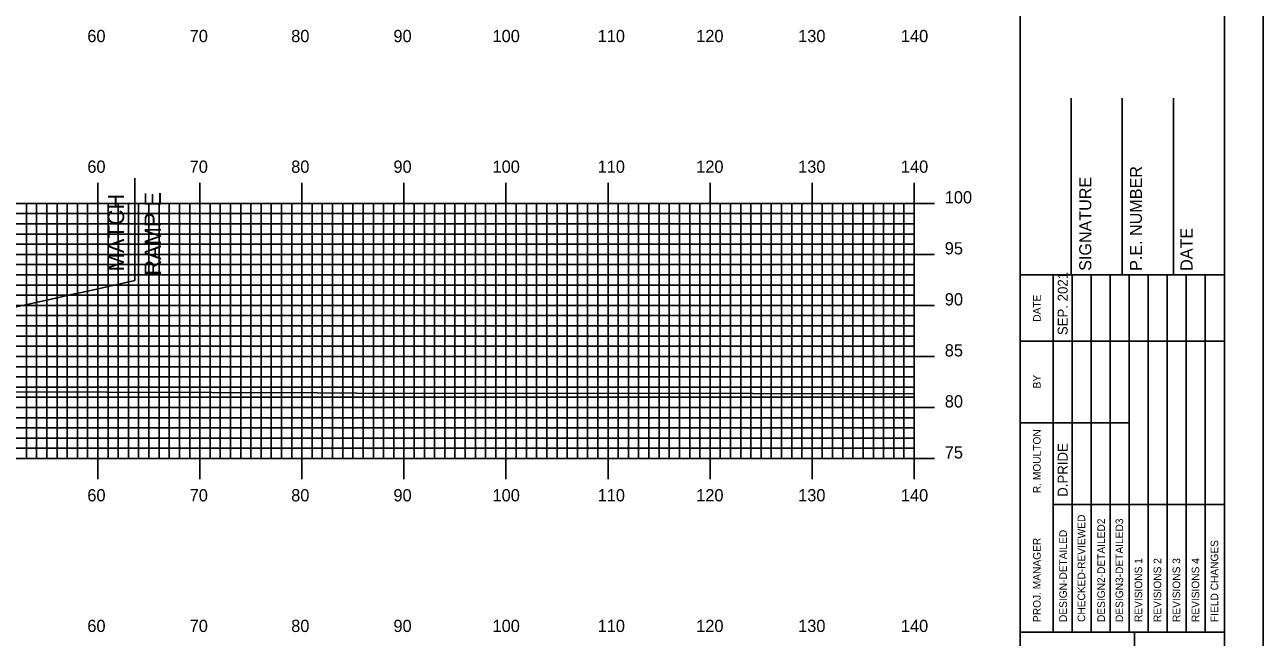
# Model space of a CAD drawing. Extents: x 1757069 to 1757412, y 442591 to 442811.
# Drawn here: x 1757287.4 to 1757408.8, y 442686.2 to 442746.2 of the extents above; entities that cross this region are included whole.
import ezdxf

# ---------------------------------------------------------------- set-up
doc = ezdxf.new("R2010")
doc.units = 0
for name, color, linetype in [('ANNOTATION', 7, 'Continuous'), ('BORDER', 7, 'Continuous'), ('D_Roadway_Centerline', 7, 'Continuous'), ('D_Roadway_SubGrade', 7, 'Continuous'), ('H_V ANNOTATION', 7, 'Continuous'), ('MAJOR', 7, 'Continuous'), ('MINOR', 7, 'Continuous'), ('PLOT BOUNDARY', 7, 'Continuous'), ('S_Roadway_Centerline', 7, 'Continuous')]:
    doc.layers.add(name, color=color, linetype=linetype)

msp = doc.modelspace()

# ---------------------------------------------------------------- linework, layer by layer
at = {"layer": 'BORDER'}
for p, q in [((1757385, 442596.67), (1757385, 442806.67)), ((1757390, 442721.67), (1757390, 442738.97)), ((1757395, 442721.67), (1757395, 442738.97)), ((1757400, 442721.67), (1757400, 442738.97)), ((1757385, 442721.67), (1757405, 442721.67)), ((1757385, 442686.67), (1757405, 442686.67)), ((1757396.18, 442616.67), (1757396.18, 442686.67))]:
    msp.add_line(p, q, dxfattribs=at)
msp.add_lwpolyline([(1757085, 442596.67), (1757405, 442596.67), (1757405, 442806.67), (1757085, 442806.67)], close=True, dxfattribs=at)
for points in [[(1757388.23, 442715.17), (1757388.23, 442721.67)], [(1757390.09, 442686.68), (1757390.09, 442721.67)], [(1757391.95, 442721.67), (1757391.95, 442686.68)], [(1757393.82, 442686.68), (1757393.82, 442721.67)], [(1757395.68, 442686.68), (1757395.68, 442721.67)], [(1757397.54, 442686.68), (1757397.54, 442721.67)], [(1757399.41, 442686.68), (1757399.41, 442721.67)], [(1757401.27, 442686.68), (1757401.27, 442721.67)], [(1757403.13, 442686.68), (1757403.13, 442721.67)], [(1757388.23, 442686.68), (1757388.23, 442720.26)], [(1757385, 442715.17), (1757405, 442715.17)], [(1757385, 442707.17), (1757388.23, 442707.17)], [(1757388.23, 442707.17), (1757395.68, 442707.17)], [(1757388.23, 442699.17), (1757405, 442699.17)]]:
    msp.add_lwpolyline(points, dxfattribs=at)
at = {"layer": 'D_Roadway_Centerline'}
msp.add_lwpolyline([(1757276.03, 442716.15), (1757277.4, 442716.46), (1757279.51, 442716.93), (1757279.72, 442716.98), (1757280.6, 442717.17), (1757280.87, 442717.24), (1757282.31, 442717.56), (1757282.61, 442717.63), (1757285.08, 442718.18), (1757285.17, 442718.2), (1757286.34, 442718.46), (1757287.81, 442718.79), (1757289.74, 442719.22), (1757290.5, 442719.39), (1757290.58, 442719.41), (1757290.73, 442719.44), (1757292.02, 442719.73), (1757293.15, 442719.98), (1757295.07, 442720.4), (1757295.77, 442720.56), (1757298.22, 442721.11)], dxfattribs=at)
at = {"layer": 'D_Roadway_SubGrade'}
msp.add_line((1757298.22, 442731.15), (1757298.22, 442721.11), dxfattribs=at)
at = {"layer": 'MAJOR'}
for p, q in [((1757294.6, 442730.67), (1757294.6, 442728.67)), ((1757304.6, 442730.67), (1757304.6, 442728.67)), ((1757314.6, 442730.67), (1757314.6, 442728.67)), ((1757324.6, 442730.67), (1757324.6, 442728.67)), ((1757334.6, 442730.67), (1757334.6, 442728.67)), ((1757344.6, 442730.67), (1757344.6, 442728.67)), ((1757354.6, 442730.67), (1757354.6, 442728.67)), ((1757364.6, 442730.67), (1757364.6, 442728.67)), ((1757374.6, 442730.67), (1757374.6, 442728.67)), ((1757094.6, 442728.67), (1757374.6, 442728.67)), ((1757094.6, 442728.67), (1757374.6, 442728.67)), ((1757294.6, 442703.67), (1757294.6, 442728.67)), ((1757304.6, 442703.67), (1757304.6, 442728.67)), ((1757314.6, 442703.67), (1757314.6, 442728.67)), ((1757324.6, 442703.67), (1757324.6, 442728.67)), ((1757334.6, 442703.67), (1757334.6, 442728.67)), ((1757344.6, 442703.67), (1757344.6, 442728.67)), ((1757354.6, 442703.67), (1757354.6, 442728.67)), ((1757364.6, 442703.67), (1757364.6, 442728.67)), ((1757376.6, 442728.67), (1757372.59, 442728.67)), ((1757374.6, 442703.67), (1757374.6, 442728.67)), ((1757374.6, 442703.67), (1757374.6, 442728.67)), ((1757094.6, 442723.67), (1757374.6, 442723.67)), ((1757376.6, 442723.67), (1757372.59, 442723.67)), ((1757094.6, 442718.67), (1757374.6, 442718.67)), ((1757376.6, 442718.67), (1757372.59, 442718.67)), ((1757094.6, 442713.67), (1757374.6, 442713.67)), ((1757376.6, 442713.67), (1757372.59, 442713.67)), ((1757094.6, 442708.67), (1757374.6, 442708.67)), ((1757376.6, 442708.67), (1757372.59, 442708.67)), ((1757094.6, 442703.67), (1757374.6, 442703.67)), ((1757094.6, 442703.67), (1757374.6, 442703.67)), ((1757294.6, 442701.66), (1757294.6, 442703.67)), ((1757304.6, 442701.66), (1757304.6, 442703.67)), ((1757314.6, 442701.66), (1757314.6, 442703.67)), ((1757324.6, 442701.66), (1757324.6, 442703.67)), ((1757334.6, 442701.66), (1757334.6, 442703.67)), ((1757344.6, 442701.66), (1757344.6, 442703.67)), ((1757354.6, 442701.66), (1757354.6, 442703.67)), ((1757364.6, 442701.66), (1757364.6, 442703.67)), ((1757376.6, 442703.67), (1757372.59, 442703.67)), ((1757374.6, 442701.66), (1757374.6, 442703.67))]:
    msp.add_line(p, q, dxfattribs=at)
at = {"layer": 'MINOR'}
for p, q in [((1757287.6, 442703.67), (1757287.6, 442728.67)), ((1757288.6, 442703.67), (1757288.6, 442728.67)), ((1757289.6, 442703.67), (1757289.6, 442728.67)), ((1757290.6, 442703.67), (1757290.6, 442728.67)), ((1757291.6, 442703.67), (1757291.6, 442728.67)), ((1757292.6, 442703.67), (1757292.6, 442728.67)), ((1757293.6, 442703.67), (1757293.6, 442728.67)), ((1757295.6, 442703.67), (1757295.6, 442728.67)), ((1757296.6, 442703.67), (1757296.6, 442728.67)), ((1757297.6, 442703.67), (1757297.6, 442728.67)), ((1757298.6, 442703.67), (1757298.6, 442728.67)), ((1757299.6, 442703.67), (1757299.6, 442728.67)), ((1757300.6, 442703.67), (1757300.6, 442728.67)), ((1757301.6, 442703.67), (1757301.6, 442728.67)), ((1757302.6, 442703.67), (1757302.6, 442728.67)), ((1757303.6, 442703.67), (1757303.6, 442728.67)), ((1757305.6, 442703.67), (1757305.6, 442728.67)), ((1757306.6, 442703.67), (1757306.6, 442728.67)), ((1757307.6, 442703.67), (1757307.6, 442728.67)), ((1757308.6, 442703.67), (1757308.6, 442728.67)), ((1757309.6, 442703.67), (1757309.6, 442728.67)), ((1757310.6, 442703.67), (1757310.6, 442728.67)), ((1757311.6, 442703.67), (1757311.6, 442728.67)), ((1757312.6, 442703.67), (1757312.6, 442728.67)), ((1757313.6, 442703.67), (1757313.6, 442728.67)), ((1757315.6, 442703.67), (1757315.6, 442728.67)), ((1757316.6, 442703.67), (1757316.6, 442728.67)), ((1757317.6, 442703.67), (1757317.6, 442728.67)), ((1757318.6, 442703.67), (1757318.6, 442728.67)), ((1757319.6, 442703.67), (1757319.6, 442728.67)), ((1757320.6, 442703.67), (1757320.6, 442728.67)), ((1757321.6, 442703.67), (1757321.6, 442728.67)), ((1757322.6, 442703.67), (1757322.6, 442728.67)), ((1757323.6, 442703.67), (1757323.6, 442728.67)), ((1757325.6, 442703.67), (1757325.6, 442728.67)), ((1757326.6, 442703.67), (1757326.6, 442728.67)), ((1757327.6, 442703.67), (1757327.6, 442728.67)), ((1757328.6, 442703.67), (1757328.6, 442728.67)), ((1757329.6, 442703.67), (1757329.6, 442728.67)), ((1757330.6, 442703.67), (1757330.6, 442728.67)), ((1757331.6, 442703.67), (1757331.6, 442728.67)), ((1757332.6, 442703.67), (1757332.6, 442728.67)), ((1757333.6, 442703.67), (1757333.6, 442728.67)), ((1757335.6, 442703.67), (1757335.6, 442728.67)), ((1757336.6, 442703.67), (1757336.6, 442728.67)), ((1757337.6, 442703.67), (1757337.6, 442728.67)), ((1757338.6, 442703.67), (1757338.6, 442728.67)), ((1757339.6, 442703.67), (1757339.6, 442728.67)), ((1757340.6, 442703.67), (1757340.6, 442728.67)), ((1757341.6, 442703.67), (1757341.6, 442728.67)), ((1757342.6, 442703.67), (1757342.6, 442728.67)), ((1757343.6, 442703.67), (1757343.6, 442728.67)), ((1757345.6, 442703.67), (1757345.6, 442728.67)), ((1757346.6, 442703.67), (1757346.6, 442728.67)), ((1757347.6, 442703.67), (1757347.6, 442728.67)), ((1757348.6, 442703.67), (1757348.6, 442728.67)), ((1757349.6, 442703.67), (1757349.6, 442728.67)), ((1757350.6, 442703.67), (1757350.6, 442728.67)), ((1757351.6, 442703.67), (1757351.6, 442728.67)), ((1757352.6, 442703.67), (1757352.6, 442728.67)), ((1757353.6, 442703.67), (1757353.6, 442728.67)), ((1757355.6, 442703.67), (1757355.6, 442728.67)), ((1757356.6, 442703.67), (1757356.6, 442728.67)), ((1757357.6, 442703.67), (1757357.6, 442728.67)), ((1757358.6, 442703.67), (1757358.6, 442728.67)), ((1757359.6, 442703.67), (1757359.6, 442728.67)), ((1757360.6, 442703.67), (1757360.6, 442728.67)), ((1757361.6, 442703.67), (1757361.6, 442728.67)), ((1757362.6, 442703.67), (1757362.6, 442728.67)), ((1757363.6, 442703.67), (1757363.6, 442728.67)), ((1757365.6, 442703.67), (1757365.6, 442728.67)), ((1757366.6, 442703.67), (1757366.6, 442728.67)), ((1757367.6, 442703.67), (1757367.6, 442728.67)), ((1757368.6, 442703.67), (1757368.6, 442728.67)), ((1757369.6, 442703.67), (1757369.6, 442728.67)), ((1757370.6, 442703.67), (1757370.6, 442728.67)), ((1757371.6, 442703.67), (1757371.6, 442728.67)), ((1757372.6, 442703.67), (1757372.6, 442728.67)), ((1757373.6, 442703.67), (1757373.6, 442728.67)), ((1757094.6, 442727.67), (1757374.6, 442727.67)), ((1757094.6, 442726.67), (1757374.6, 442726.67)), ((1757374.6, 442727.67), (1757372.59, 442727.67)), ((1757374.6, 442726.67), (1757372.59, 442726.67)), ((1757094.6, 442725.67), (1757374.6, 442725.67)), ((1757374.6, 442725.67), (1757372.59, 442725.67)), ((1757094.6, 442724.67), (1757374.6, 442724.67)), ((1757374.6, 442724.67), (1757372.59, 442724.67)), ((1757094.6, 442722.67), (1757374.6, 442722.67)), ((1757374.6, 442722.67), (1757372.59, 442722.67)), ((1757094.6, 442721.67), (1757374.6, 442721.67)), ((1757094.6, 442720.67), (1757374.6, 442720.67)), ((1757374.6, 442721.67), (1757372.59, 442721.67)), ((1757374.6, 442720.67), (1757372.59, 442720.67)), ((1757094.6, 442719.67), (1757374.6, 442719.67)), ((1757374.6, 442719.67), (1757372.59, 442719.67)), ((1757094.6, 442717.67), (1757374.6, 442717.67)), ((1757374.6, 442717.67), (1757372.59, 442717.67)), ((1757094.6, 442716.67), (1757374.6, 442716.67)), ((1757094.6, 442715.67), (1757374.6, 442715.67)), ((1757374.6, 442716.67), (1757372.59, 442716.67)), ((1757374.6, 442715.67), (1757372.59, 442715.67)), ((1757094.6, 442714.67), (1757374.6, 442714.67)), ((1757374.6, 442714.67), (1757372.59, 442714.67)), ((1757094.6, 442712.67), (1757374.6, 442712.67)), ((1757374.6, 442712.67), (1757372.59, 442712.67)), ((1757094.6, 442711.67), (1757374.6, 442711.67)), ((1757374.6, 442711.67), (1757372.59, 442711.67)), ((1757094.6, 442710.67), (1757374.6, 442710.67)), ((1757094.6, 442709.67), (1757374.6, 442709.67)), ((1757374.6, 442710.67), (1757372.59, 442710.67)), ((1757374.6, 442709.67), (1757372.59, 442709.67)), ((1757094.6, 442707.67), (1757374.6, 442707.67)), ((1757374.6, 442707.67), (1757372.59, 442707.67)), ((1757094.6, 442706.67), (1757374.6, 442706.67)), ((1757374.6, 442706.67), (1757372.59, 442706.67)), ((1757094.6, 442705.67), (1757374.6, 442705.67)), ((1757374.6, 442705.67), (1757372.59, 442705.67)), ((1757094.6, 442704.67), (1757374.6, 442704.67)), ((1757374.6, 442704.67), (1757372.59, 442704.67))]:
    msp.add_line(p, q, dxfattribs=at)
at = {"layer": 'PLOT BOUNDARY'}
msp.add_lwpolyline([(1757068.81, 442590.55), (1757408.81, 442590.55), (1757408.81, 442810.55), (1757068.81, 442810.55)], close=True, dxfattribs=at)
at = {"layer": 'S_Roadway_Centerline'}
msp.add_lwpolyline([(1757094.6, 442709.18), (1757117.33, 442709.26), (1757140.81, 442709.08), (1757149.64, 442709.11), (1757165.92, 442709.27), (1757181.5, 442709.37), (1757191.75, 442709.55), (1757206.83, 442709.71), (1757242.69, 442709.94), (1757244.49, 442709.95), (1757245.67, 442709.95), (1757285.02, 442710.21), (1757285.15, 442710.21), (1757316.08, 442710.1), (1757319.99, 442710.08), (1757358.79, 442710.05), (1757374.6, 442710.01)], dxfattribs=at)

# ---------------------------------------------------------------- texts
at = {"layer": 'ANNOTATION'}
for s, p in [('MATCH', (1757297.18, 442722.01)), ('RAMP E', (1757300.78, 442721.59))]:
    msp.add_text(s, height=1.6, rotation=90, dxfattribs=at).set_placement(p)
at = {"layer": 'BORDER'}
for s, height, p in [('P.E. NUMBER', 1.1811, (1757396.92, 442722.06)), ('SIGNATURE', 1.181, (1757391.96, 442722.06)), ('DATE', 1.181, (1757401.88, 442722.06)), ('SEP. 2021', 0.969, (1757389.64, 442715.76)), ('DATE', 0.743, (1757387, 442717.08)), ('BY', 0.743, (1757387, 442710.54)), ('R. MOULTON', 0.745, (1757387, 442700.28)), ('D.PRIDE', 0.969, (1757389.64, 442699.92)), ('CHECKED-REVIEWED', 0.7455, (1757391.36, 442687.65)), ('DESIGN2-DETAILED2', 0.7455, (1757393.3, 442687.65)), ('DESIGN3-DETAILED3', 0.7455, (1757395.08, 442687.65)), ('DESIGN-DETAILED', 0.7455, (1757389.57, 442687.65)), ('PROJ. MANAGER', 0.7455, (1757387, 442687.65)), ('FIELD CHANGES', 0.7455, (1757404.4, 442687.65)), ('REVISIONS 1', 0.7455, (1757396.95, 442687.65)), ('REVISIONS 2', 0.7455, (1757398.81, 442687.65)), ('REVISIONS 3', 0.7455, (1757400.67, 442687.65)), ('REVISIONS 4', 0.7455, (1757402.54, 442687.65))]:
    msp.add_text(s, height=height, rotation=90, dxfattribs=at).set_placement(p)
at = {"layer": 'H_V ANNOTATION'}
for s, p in [('60', (1757293.57, 442744.47)), ('70', (1757303.6, 442744.47)), ('80', (1757313.55, 442744.47)), ('90', (1757323.57, 442744.47)), ('100', (1757333.28, 442744.47)), ('110', (1757343.58, 442744.47)), ('120', (1757353.24, 442744.47)), ('130', (1757363.23, 442744.47)), ('140', (1757373.3, 442744.47)), ('60', (1757293.57, 442731.67)), ('70', (1757303.6, 442731.67)), ('80', (1757313.55, 442731.67)), ('90', (1757323.57, 442731.67)), ('100', (1757333.28, 442731.67)), ('110', (1757343.58, 442731.67)), ('120', (1757353.24, 442731.67)), ('130', (1757363.23, 442731.67)), ('140', (1757373.3, 442731.67)), ('100', (1757377.6, 442728.67)), ('95', (1757377.6, 442723.67)), ('90', (1757377.6, 442718.67)), ('85', (1757377.6, 442713.67)), ('80', (1757377.6, 442708.67)), ('75', (1757377.6, 442703.67)), ('60', (1757293.57, 442699.47)), ('70', (1757303.6, 442699.47)), ('80', (1757313.55, 442699.47)), ('90', (1757323.57, 442699.47)), ('100', (1757333.28, 442699.47)), ('110', (1757343.58, 442699.47)), ('120', (1757353.24, 442699.47)), ('130', (1757363.23, 442699.47)), ('140', (1757373.3, 442699.47)), ('60', (1757293.57, 442686.67)), ('70', (1757303.6, 442686.67)), ('80', (1757313.55, 442686.67)), ('90', (1757323.57, 442686.67)), ('100', (1757333.28, 442686.67)), ('110', (1757343.58, 442686.67)), ('120', (1757353.24, 442686.67)), ('130', (1757363.23, 442686.67)), ('140', (1757373.3, 442686.67))]:
    msp.add_text(s, height=1.2, dxfattribs=at).set_placement(p)

doc.saveas('drawing.dxf')
